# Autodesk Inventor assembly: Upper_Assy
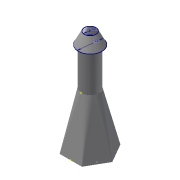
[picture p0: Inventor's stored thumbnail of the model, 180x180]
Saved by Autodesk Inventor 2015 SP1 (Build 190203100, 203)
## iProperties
Created: 2013-06
Part Number: Upper_Assy
Document SubType Name: Assembly
Designer: BarryWSUK
Author: BarryWSUK
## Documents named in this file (6)
- \\psf\Home\Documents\Inventor\Sau Paulo Chimnea\Upper_Assy.iam
- \\psf\Home\Documents\Inventor\Sau Paulo Chimnea\Hex to Round Half.ipt
- \\psf\Home\Documents\Inventor\Sau Paulo Chimnea\Flue.ipt
- \\psf\Home\Documents\Inventor\Sau Paulo Chimnea\Lid Straps.ipt
- \\psf\Home\Documents\Inventor\Sau Paulo Chimnea\Lid.ipt
- \\psf\Home\Documents\Inventor\Sau Paulo Chimnea\IFI 520 - 43 x 3.3(3).ipt
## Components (15 placed, 5 different names)
1. Hex to Round Half:1 — Mate:1, Mate:2, Mate:6
2. Flue:1 — Mate:1, Mate:2, Tangent:1, Angle:1, Mate:4, Flush:2, Mate:5, Mate:6, Mate:7, Tangent:2
3. Lid:1 — Mate:4, Flush:2, Mate:5, Flush:3
4. Lid Straps:2 — Tangent:1, Angle:1, Mate:7
5. Lid Straps:3 — Mate:8, Insert:1
6. Lid Straps:4 — Flush:3
7. IFI 520 - 43 x 3.3(3):1 — Insert:1
8. IFI 520 - 43 x 3.3(3):5
9. IFI 520 - 43 x 3.3(3):8
10. IFI 520 - 43 x 3.3(3):3 — Tangent:2, Mate:8
11. IFI 520 - 43 x 3.3(3):4
12. IFI 520 - 43 x 3.3(3):6
13. IFI 520 - 43 x 3.3(3):7
14. IFI 520 - 43 x 3.3(3):9
15. IFI 520 - 43 x 3.3(3):10
## Component patterns: Component Pattern 3:2 (2 elements), Component Pattern 3:3 (2 elements)
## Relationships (13: Mate 7, Tangent 2, Flush 2, Angle 1, Insert 1)
- Mate:1: Hex to Round Half:1 ↔ Flue:1
- Mate:2: Hex to Round Half:1 ↔ Flue:1
- Tangent:1: Flue:1 ↔ Lid Straps:2
- Angle:1: Flue:1 ↔ Lid Straps:2
- Mate:4: Flue:1 ↔ Lid:1
- Flush:2: Flue:1 ↔ Lid:1
- Mate:5: Flue:1 ↔ Lid:1
- Mate:6: Hex to Round Half:1 ↔ Flue:1
- Mate:7: Flue:1 ↔ Lid Straps:2
- Tangent:2: Flue:1 ↔ IFI 520 - 43 x 3.3(3):3
- Mate:8: Lid Straps:3 ↔ IFI 520 - 43 x 3.3(3):3
- Flush:3: Lid:1 ↔ Lid Straps:4
- Insert:1: Lid Straps:3 ↔ IFI 520 - 43 x 3.3(3):1
